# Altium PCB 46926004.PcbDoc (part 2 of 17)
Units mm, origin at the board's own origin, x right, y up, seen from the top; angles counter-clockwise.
Board outline 250 x 200 mm, 6 copper layers (Top Layer, INT1_GND, INT2_SIG, INT3_SIG, INT4_GND, Bottom Layer), stack 1.71 mm thick; 1450 components, 1293 nets, 5656 pads, 2307 vias.
Unrouted connection lines stored in the file: 2.
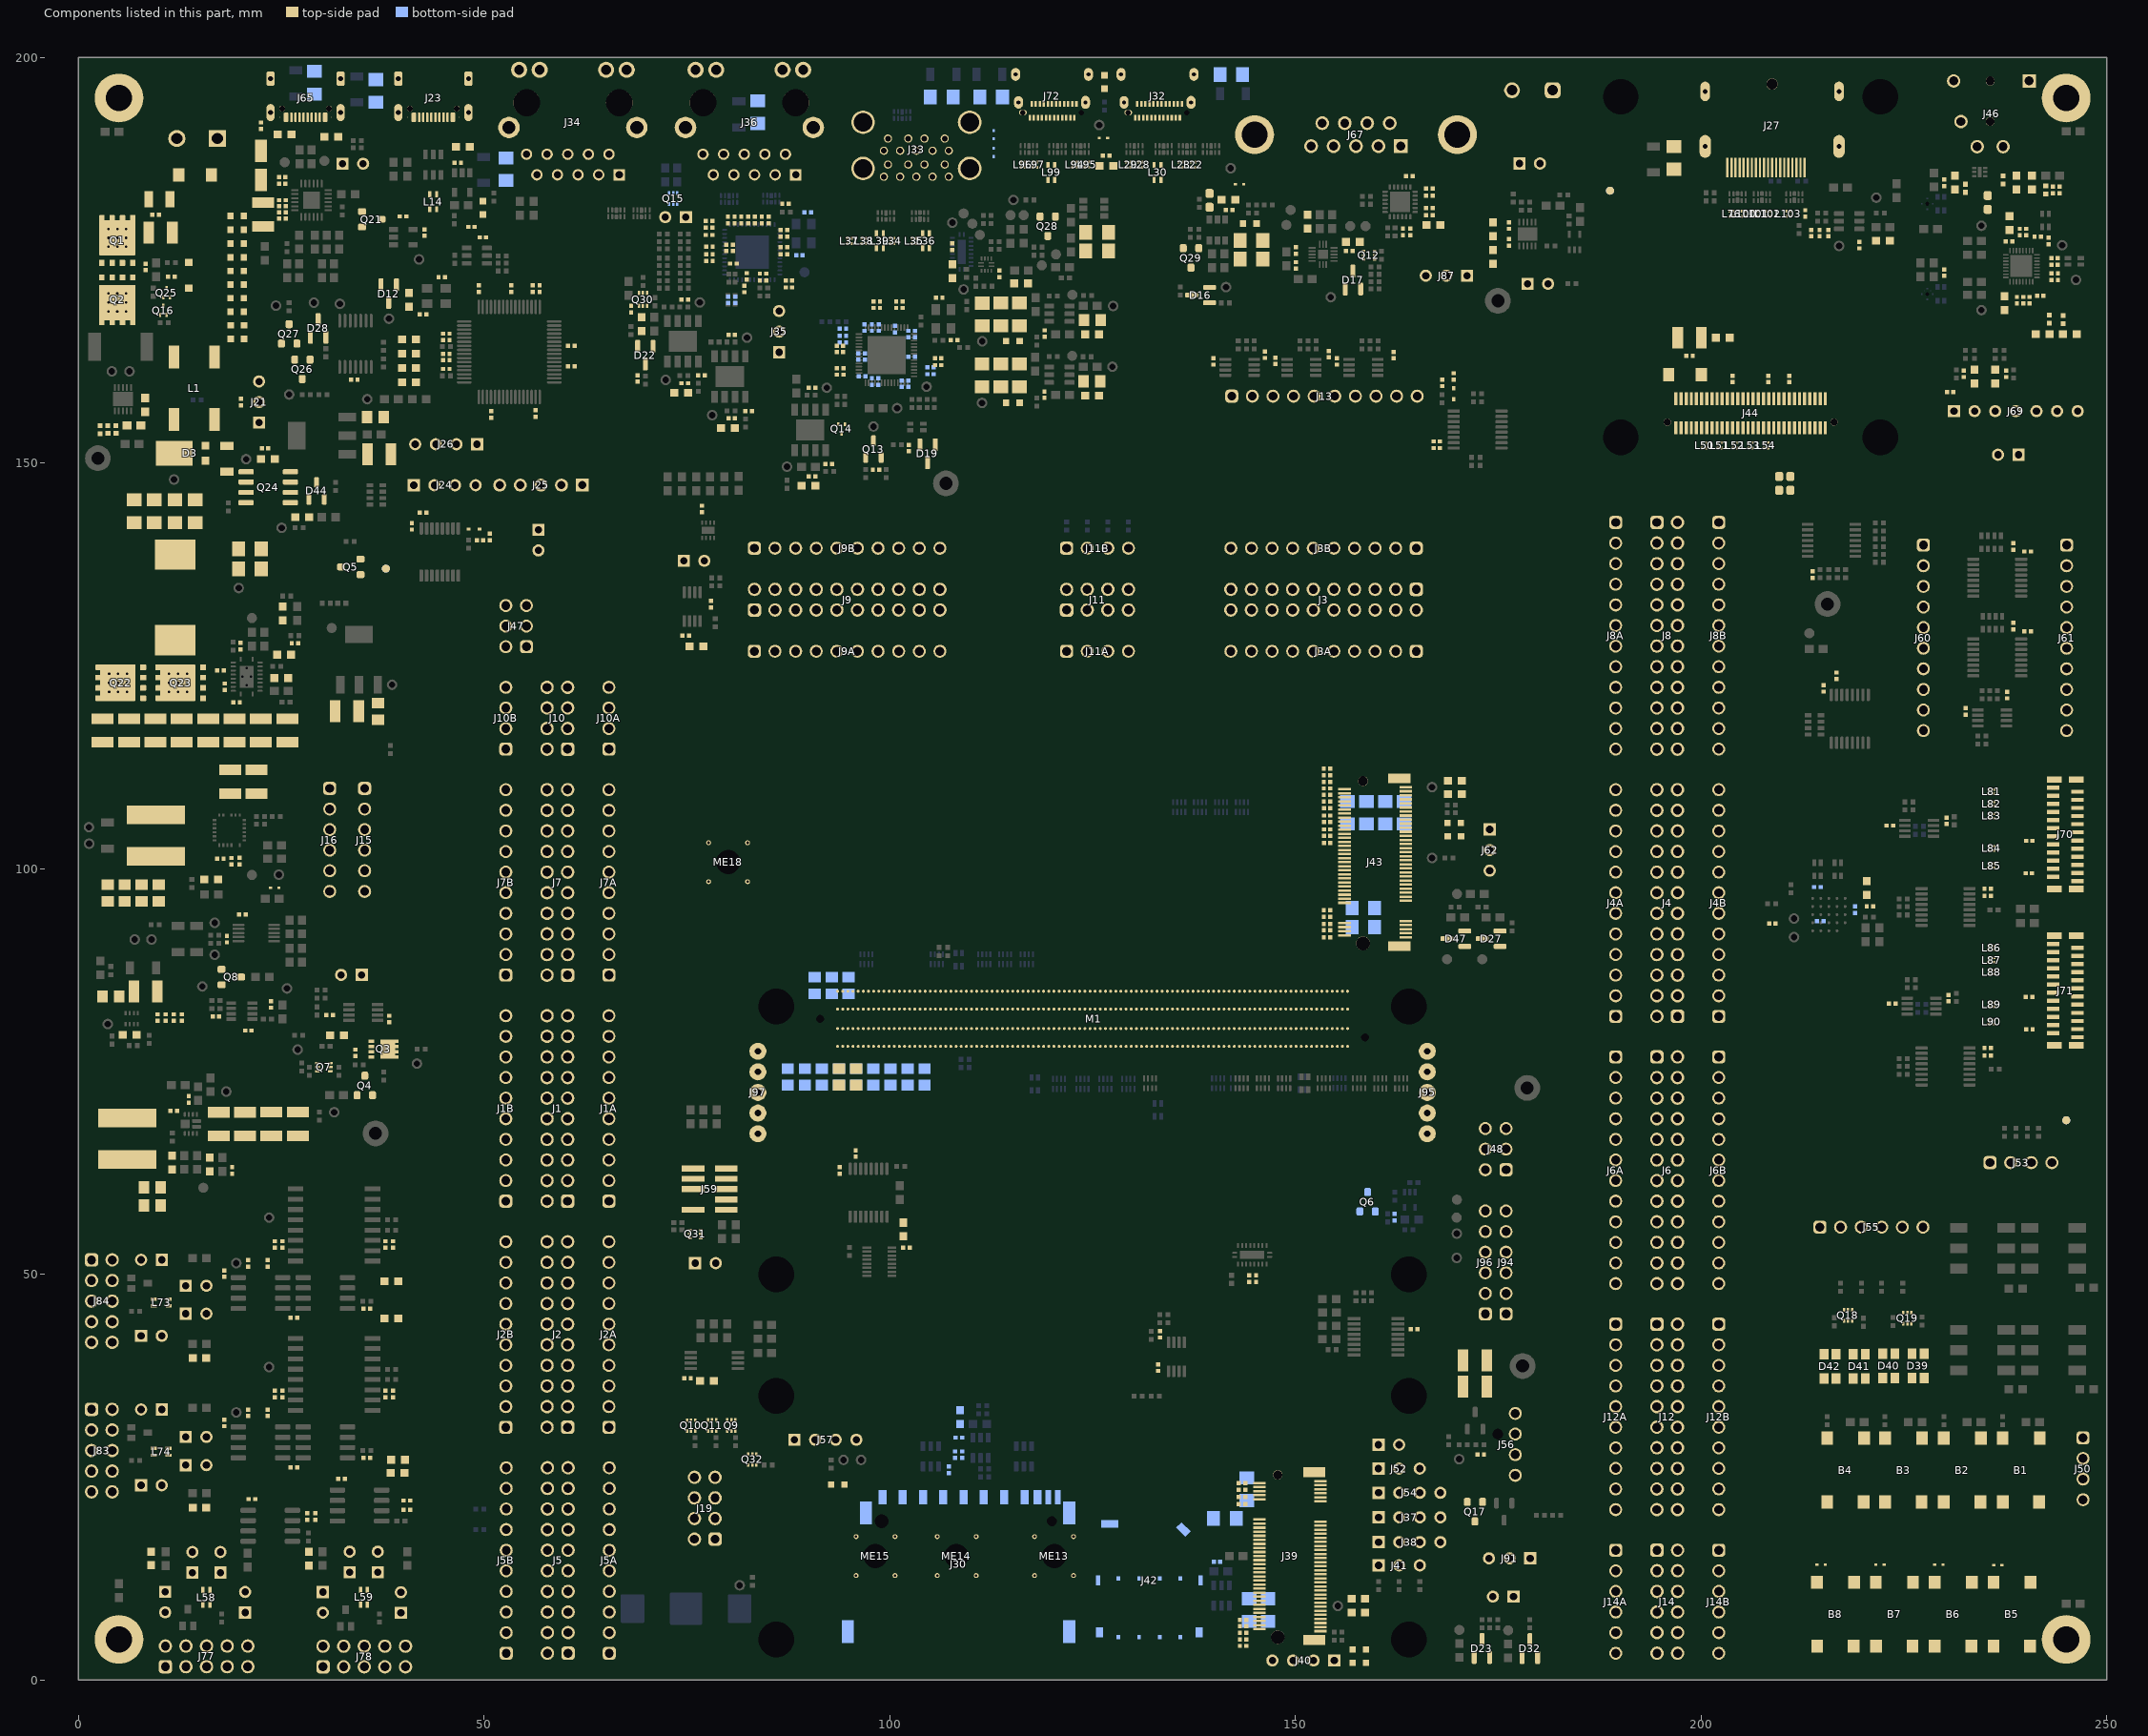
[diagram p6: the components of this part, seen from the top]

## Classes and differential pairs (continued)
differential pair PCIE_1_L1_RX: +PCIE_1_L1_RX_P -PCIE_1_L1_RX_N
differential pair FTUSB: +FTUSB_P -FTUSB_N
differential pair FT_USB: +FT_USB_P -FT_USB_N
differential pair ETH2_D3: +ETH2_D3_P -ETH2_D3_N
differential pair ETH2_D2: +ETH2_D2_P -ETH2_D2_N
differential pair ETH2_D1: +ETH2_D1_P -ETH2_D1_N
differential pair ETH2_D0: +ETH2_D0_P -ETH2_D0_N
differential pair DSI__D3: +DSI__D3_P -DSI__D3_N
differential pair DSI__D2: +DSI__D2_P -DSI__D2_N
differential pair DSI__D1: +DSI__D1_P -DSI__D1_N
differential pair DSI__D0: +DSI__D0_P -DSI__D0_N
differential pair DSI__CLK: +DSI__CLK_P -DSI__CLK_N
differential pair DP_1_LANE3: +DP_1_LANE3_P -DP_1_LANE3_N
differential pair DP_1_LANE2: +DP_1_LANE2_P -DP_1_LANE2_N
differential pair DP_1_LANE1: +DP_1_LANE1_P -DP_1_LANE1_N
differential pair DP_1_LANE0: +DP_1_LANE0_P -DP_1_LANE0_N
differential pair DP_1_AUX: +DP_1_AUX_P -DP_1_AUX_N
differential pair CSI_C2_D3: +CSI_C2_D3_P -CSI_C2_D3_N
differential pair CSI_C2_D2: +CSI_C2_D2_P -CSI_C2_D2_N
differential pair CSI_C2_D1: +CSI_C2_D1_P -CSI_C2_D1_N
differential pair CSI_C2_D0: +CSI_C2_D0_P -CSI_C2_D0_N
differential pair CSI_C2_CLK: +CSI_C2_CLK_P -CSI_C2_CLK_N
differential pair CSI_C1_D3: +CSI_C1_D3_P -CSI_C1_D3_N
differential pair CSI_C1_D2: +CSI_C1_D2_P -CSI_C1_D2_N
differential pair CSI_C1_D1: +CSI_C1_D1_P -CSI_C1_D1_N
differential pair CSI_C1_D0: +CSI_C1_D0_P -CSI_C1_D0_N
differential pair CSI_C1_CLK: +CSI_C1_CLK_P -CSI_C1_CLK_N
differential pair CSI_2_D3: +CSI_2_D3_P -CSI_2_D3_N
differential pair CSI_2_D2: +CSI_2_D2_P -CSI_2_D2_N
differential pair CSI_2_D1: +CSI_2_D1_P -CSI_2_D1_N
differential pair CSI_2_D0: +CSI_2_D0_P -CSI_2_D0_N
differential pair CSI_2_CLK: +CSI_2_CLK_P -CSI_2_CLK_N
differential pair USB_2_D: +USB_2_D_P -USB_2_D_N
differential pair USB_1_D: +USB_1_D_P -USB_1_D_N
differential pair PCIE_1_L0_TX: +PCIE_1_L0_TX_P -PCIE_1_L0_TX_N
differential pair PCIE_1_L0_RX: +PCIE_1_L0_RX_P -PCIE_1_L0_RX_N
differential pair PCIE_1_CLK: +PCIE_1_CLK_P -PCIE_1_CLK_N
differential pair ETH_1_MDI3: +ETH_1_MDI3_P -ETH_1_MDI3_N
differential pair ETH_1_MDI2: +ETH_1_MDI2_P -ETH_1_MDI2_N
differential pair ETH_1_MDI1: +ETH_1_MDI1_P -ETH_1_MDI1_N
differential pair ETH_1_MDI0: +ETH_1_MDI0_P -ETH_1_MDI0_N
differential pair DSI_1_D3: +DSI_1_D3_P -DSI_1_D3_N
differential pair DSI_1_D2: +DSI_1_D2_P -DSI_1_D2_N
differential pair DSI_1_D1: +DSI_1_D1_P -DSI_1_D1_N
differential pair DSI_1_D0: +DSI_1_D0_P -DSI_1_D0_N
differential pair DSI_1_CLK: +DSI_1_CLK_P -DSI_1_CLK_N
differential pair CSI_1_D3: +CSI_1_D3_P -CSI_1_D3_N
differential pair CSI_1_D2: +CSI_1_D2_P -CSI_1_D2_N
differential pair CSI_1_D1: +CSI_1_D1_P -CSI_1_D1_N
differential pair CSI_1_D0: +CSI_1_D0_P -CSI_1_D0_N
differential pair CSI_1_CLK: +CSI_1_CLK_P -CSI_1_CLK_N

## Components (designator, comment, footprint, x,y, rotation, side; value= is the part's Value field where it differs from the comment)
B1 "B3FS-1010P" OMRONSW_B3FS-1010P 239.448,25.875 r90 top
B2 "B3FS-1010P" OMRONSW_B3FS-1010P 232.198,25.875 r90 top
B3 "B3FS-1010P" OMRONSW_B3FS-1010P 224.948,25.875 r90 top
B4 "B3FS-1010P" OMRONSW_B3FS-1010P 217.823,25.875 r90 top
B5 "B3FS-1010P" OMRONSW_B3FS-1010P 238.325,8.1 r90 top locked
B6 "B3FS-1010P" OMRONSW_B3FS-1010P 231.075,8.1 r90 top locked
B7 "B3FS-1010P" OMRONSW_B3FS-1010P 223.825,8.1 r90 top locked
B8 "B3FS-1010P" OMRONSW_B3FS-1010P 216.575,8.1 r90 top locked
C1 "10uF/50V" CAPC3225N 33.1,119.425 r180 top
C2 "10uF/50V" CAPC3225N 10.125,178.425 r180 top
C3 "100nF" C0402_CAPC1005L 9.525,180.6 r0 top
C4 "1314-Cap-0805-22uF/16V" C/0805 36.925,119.375 r90 top value=22uF/16V
C5 "100nF" C0402_CAPC1005L 8.305,174.17 r270 top
C6 "1573-Cap-0402-1.5nF" C0402_CAPC1005L 11.46,172.97 r180 top value=1.5nF
C7 "100nF" C0402_CAPC1005L 20.025,157.525 r90 top
C8 "100nF" C0402_CAPC1005L 38.3,81.475 r90 top
C9 "100nF" C0402_CAPC1005L 30.977,81.975 r0 top
C10 "100nF" C0402_CAPC1005L 34.125,77.3 r90 top
C11 "100nF" C0402_CAPC1005L 18.3,91.325 r270 top
C12 "100nF" C0402_CAPC1005L 20.225,94.35 r180 top
C13 "1314-Cap-0805-22uF/16V" C/0805 9.128,60.725 r180 top value=22uF/16V
C14 "1314-Cap-0805-22uF/16V" C/0805 4,84.25 r0 top value=22uF/16V
C15 "1314-Cap-0805-22uF/16V" C/0805 9.128,58.475 r180 top value=22uF/16V
C16 "100nF" C/0603 6.324,79.535 r180 top value=470pF
C17 "100nF" C0402_CAPC1005L 13.6,71.575 r270 top
C18 "10uF/50V" CAPC3225N 172.125,39.4 r0 top
C19 "10uF/50V" CAPC3225N 172.125,36.15 r0 top
C20 "10uF/50V" CAPC3225N 18.7,110.725 r270 top
C21 "22uF/6.3V" C0402_CAPC1005L 12.755,81.653 r90 top
C22 "22uF/6.3V" C0402_CAPC1005L 18.866,100.925 r90 top
C23 "10uF/50V" CAPC3225N 21.925,110.725 r270 top
C24 "22uF/6.3V" C0402_CAPC1005L 11.755,81.653 r90 top
C25 "22uF/6.3V" C0402_CAPC1005L 10.755,81.653 r90 top
C26 "22uF/6.3V" C0402_CAPC1005L 9.755,81.653 r90 top
C27 "10nF" C0402_CAPC1005L 19.869,100.928 r90 top
C28 "100uF/10V" C/1206 144.57,177.436 r180 top
C29 "100nF" C0402_CAPC1005L 11.755,70.175 r0 top
C30 "2163-Cap-0603-10uF/16V" C/0603 11.525,63.8 r90 top value=10uF/16V
C31 "2093-Cap-0603-4.7uF/10V" C/0603 141.72,182.452 r180 top value=4.7uF/10V
C32 "100uF/10V" C/1206 115.984,160.805 r270 top
C33 "100uF/10V" C/1206 116,168.324 r270 top
C34 "100nF" C0402_CAPC1005L 17.491,101.25 r0 top
C35 "2093-Cap-0603-4.7uF/10V" C/0603 126.696,186.65 r180 top value=4.7uF/10V
C36 "0318-Cap-0402-1nF/50V" C0402_CAPC1005L 18.954,62.817 r90 top value=1nF
C37 "1567-Cap-0603-47pF/100V" C/0603 16.175,63.525 r270 top value=47pF
C38 "0213-Cap-0603-220pF/50V" C/0603 16.366,98.675 r180 top value=220pF
C39 "22uF/6.3V" C0402_CAPC1005L 40,180.4 r0 top
C40 "10uF/50V" CAPC3225N 27.032,68.531 r90 top
C41 "22uF/6.3V" C0402_CAPC1005L 42.666,178.411 r270 top
C42 "1647-Cap-0805-47uF/10V" C/0805 9.9,97 r90 top value=47uF/10V
C43 "10uF/50V" CAPC3225N 23.786,68.531 r90 top
C44 "1647-Cap-0805-47uF/10V" C/0805 7.8,97 r90 top value=47uF/10V
C45 "1647-Cap-0805-47uF/10V" C/0805 5.7,97 r90 top value=47uF/10V
C46 "1647-Cap-0805-47uF/10V" C/0805 3.6,97 r90 top value=47uF/10V
C47 "100nF" C0402_CAPC1005L 23.725,83.275 r270 top
C48 "100nF" C0402_CAPC1005L 20.95,80.05 r0 top
C49 "1644-Cap-0402-1uF/16V" C0402_CAPC1005L 16.95,81.775 r0 top value=1uF/16V
C50 "0000-Cap-0603-DNP" C/0603 31.875,79.45 r0 top value=DNP
C51 "14x 22uF/16V" C/0805 90.75,85.6 r270 bottom value=22uF/16V
C52 "1314-Cap-0805-22uF/16V" C/0805 91.639,74.35 r90 bottom value=22uF/16V
C53 "1314-Cap-0805-22uF/16V" C/0805 89.539,74.35 r90 bottom value=22uF/16V
C54 "1314-Cap-0805-22uF/16V" C/0805 87.425,74.35 r90 bottom value=22uF/16V
C55 "1314-Cap-0805-22uF/16V" C/0805 104.289,74.35 r90 bottom value=22uF/16V
C56 "1314-Cap-0805-22uF/16V" C/0805 93.739,74.35 r90 bottom value=22uF/16V
C57 "1314-Cap-0805-22uF/16V" C/0805 95.865,74.35 r90 top value=22uF/16V
C58 "1314-Cap-0805-22uF/16V" C/0805 93.739,74.35 r90 top value=22uF/16V
C59 "1314-Cap-0805-22uF/16V" C/0805 97.989,74.35 r90 bottom value=22uF/16V
C60 "1314-Cap-0805-22uF/16V" C/0805 100.089,74.35 r90 bottom value=22uF/16V
C61 "1314-Cap-0805-22uF/16V" C/0805 92.85,85.6 r270 bottom value=22uF/16V
C62 "1314-Cap-0805-22uF/16V" C/0805 95.865,74.35 r90 bottom value=22uF/16V
C63 "1314-Cap-0805-22uF/16V" C/0805 94.925,85.6 r270 bottom value=22uF/16V
C64 "1314-Cap-0805-22uF/16V" C/0805 102.189,74.35 r90 bottom value=22uF/16V
C65 "100nF" C0402_CAPC1005L 139.885,162.533 r270 top
C66 "100nF" C0402_CAPC1005L 147.515,162.6 r270 top
C67 "100nF" C0402_CAPC1005L 146.234,163.355 r270 top
C68 "100nF" C0402_CAPC1005L 154.097,163.42 r270 top
C69 "100nF" C0402_CAPC1005L 155.125,162.533 r270 top
C70 "100nF" C0402_CAPC1005L 162.1,163.3 r270 top
C71 "0567-Cap-1206-1nF/2KV" C/1206 36.65,195.86 r270 bottom value=1nF/2KV
C72 "22uF/6.3V" C0402_CAPC1005L 46.753,187.03 r0 top
C73 "22uF/6.3V" C0402_CAPC1005L 48.437,179.109 r0 top
C74 "100nF" C0402_CAPC1005L 49.85,177.816 r0 top
C75 "22uF/6.3V" C0402_CAPC1005L 45.34,162.7 r0 top
C76 "22uF/6.3V" C0402_CAPC1005L 45.34,165.175 r0 top
C77 "1555-Cap-0402-20pF" C0402_CAPC1005L 42.49,168.325 r180 top value=20pF
C78 "100nF" C0402_CAPC1005L 56,171.5 r270 top
C79 "100nF" C0402_CAPC1005L 45.34,163.475 r0 top
C80 "100nF" C0402_CAPC1005L 45.34,165.95 r0 top
C81 "1555-Cap-0402-20pF" C0402_CAPC1005L 44.79,172.9 r180 top value=20pF
C82 "22uF/6.3V" C0402_CAPC1005L 56.85,171.5 r270 top
C83 "100nF" C0402_CAPC1005L 45.34,161.6 r0 top
C84 "100nF" C0402_CAPC1005L 60.75,161.95 r180 top
C85 "100nF" C0402_CAPC1005L 50.865,156 r90 top
C86 "100nF" C0402_CAPC1005L 49.34,171.5 r270 top
C87 "100nF" C0402_CAPC1005L 56.365,156.1 r90 top
C88 "100nF" C0402_CAPC1005L 60.75,164.45 r180 top
C89 "100nF" C0402_CAPC1005L 53.34,171.5 r270 top
C90 "22uF/6.3V" C0402_CAPC1005L 108.514,29.88 r0 bottom
C91 "100nF" C0402_CAPC1005L 107.3,25.92 r90 bottom
C92 "100nF" C0402_CAPC1005L 74.85,128.755 r0 top
C93 "100nF" C0402_CAPC1005L 77.96,132.613 r90 top
C94 "0354-Cap-0402-4.7uF/6.3V" C0402_CAPC1005L 150.071,176.215 r270 top value=4.7uF/6.3V
C95 "2234-Cap-0402-2.2uF/10V" C0402_CAPC1005L 150.071,174.365 r90 top value=2.2uF/10V
C96 "0354-Cap-0402-4.7uF/6.3V" C0402_CAPC1005L 68.124,168.989 r90 top value=4.7uF/6.3V
C97 "100nF" C0402_CAPC1005L 156.646,176.123 r180 top
C98 "0000-Cap-0603-DNP" C/0603 69.441,167.11 r90 top value=DNP
C99 "100nF" C0402_CAPC1005L 86.95,177.925 r0 top
C100 "100nF" C0402_CAPC1005L 141.828,181.2 r180 top
C101 "0567-Cap-1206-1nF/2KV" C/1206 142.1,197.9 r180 bottom value=1nF/2KV
C102 "0354-Cap-0402-4.7uF/6.3V" C0402_CAPC1005L 98.659,166.7 r90 bottom value=4.7uF/6.3V
C103 "0354-Cap-0402-4.7uF/6.3V" C0402_CAPC1005L 102.7,163.118 r0 bottom value=4.7uF/6.3V
C104 "0354-Cap-0402-4.7uF/6.3V" C0402_CAPC1005L 102.375,151.849 r90 top value=4.7uF/6.3V
C105 "0354-Cap-0402-4.7uF/6.3V" C0402_CAPC1005L 94.222,166.56 r0 bottom value=4.7uF/6.3V
C106 "0354-Cap-0402-4.7uF/6.3V" C0402_CAPC1005L 105.024,161.8 r180 bottom value=4.7uF/6.3V
C107 "100nF" C0402_CAPC1005L 100.637,166.5 r90 bottom
C108 "22uF/6.3V" C0402_CAPC1005L 90.426,148.359 r0 top
C109 "100nF" C0402_CAPC1005L 97.794,166.7 r90 bottom
C110 "22uF/6.3V" C0402_CAPC1005L 92.486,149.866 r180 top
C111 "100nF" C0402_CAPC1005L 97.796,160.04 r270 bottom
C112 "100nF" C0402_CAPC1005L 98.576,160.04 r270 bottom
C113 "100nF" C0402_CAPC1005L 94.222,164.86 r0 bottom
C114 "100nF" C0402_CAPC1005L 96.905,166.7 r90 bottom
C115 "100nF" C0402_CAPC1005L 102.7,165.5 r0 bottom
C116 "100nF" C0402_CAPC1005L 96.534,162.735 r180 bottom
C117 "100nF" C0402_CAPC1005L 105.967,162.075 r180 top
C118 "100nF" C0402_CAPC1005L 94.222,165.694 r0 bottom
C119 "100nF" C0402_CAPC1005L 96.534,163.493 r180 bottom
C120 "100nF" C0402_CAPC1005L 105.967,162.939 r180 top
C121 "0318-Cap-0402-1nF/50V" C0402_CAPC1005L 102.7,166.3 r180 bottom value=1nF
C122 "22uF/6.3V" C0402_CAPC1005L 90.426,159.282 r0 top
C123 "100nF" C0402_CAPC1005L 96.593,160.693 r180 bottom
C124 "0318-Cap-0402-1nF/50V" C0402_CAPC1005L 105.024,160.953 r0 bottom value=1nF
C125 "0318-Cap-0402-1nF/50V" C0402_CAPC1005L 101.875,159.375 r180 bottom value=1nF
C126 "1554-Cap-0402-30pF" C0402_CAPC1005L 106.095,170.37 r0 top value=30pF
C127 "0318-Cap-0402-1nF/50V" C0402_CAPC1005L 101.875,160.175 r180 bottom value=1nF
C128 "1554-Cap-0402-30pF" C0402_CAPC1005L 107.942,165.138 r0 top value=30pF
C129 "100nF" C0402_CAPC1005L 98.311,149.198 r0 top
C130 "100nF" C0402_CAPC1005L 77.725,178.11 r180 top
C131 "100nF" C0402_CAPC1005L 100.792,169.525 r270 top
C132 "100nF" C0402_CAPC1005L 97.992,169.525 r270 top
C133 "100nF" C0402_CAPC1005L 93.867,163.7 r0 top
C134 "100nF" C0402_CAPC1005L 93.892,160.897 r0 top
C135 "100nF" C0402_CAPC1005L 101.567,169.525 r270 top
C136 "100nF" C0402_CAPC1005L 98.792,169.525 r270 top
C137 "100nF" C0402_CAPC1005L 93.867,164.45 r0 top
C138 "100nF" C0402_CAPC1005L 93.892,161.697 r0 top
C139 "22uF/6.3V" C/0805 124.931,160.082 r180 top value=22uF/16V
C140 "22uF/6.3V" C/0805 124.95,167.613 r180 top value=22uF/16V
C141 "1644-Cap-0402-1uF/16V" C0402_CAPC1005L 86.95,178.725 r180 top value=1uF/16V
C142 "1644-Cap-0402-1uF/16V" C0402_CAPC1005L 77.725,179.01 r0 top value=1uF/16V
C143 "1646-Cap-0402-10uF/6.3V" C0402_CAPC1005L 77.725,179.86 r0 top value=10uF/6.3V
C144 "100nF" C0402_CAPC1005L 229.95,184.55 r270 top
C145 "100nF" C0402_CAPC1005L 119.069,158.43 r90 top
C146 "100nF" C0402_CAPC1005L 119.112,165.959 r90 top
C147 "100nF" C0402_CAPC1005L 80.95,170.125 r270 bottom
C148 "0567-Cap-1206-1nF/2KV" C/1206 52.7,186.22 r90 bottom value=1nF/2KV
C149 "22uF/6.3V" C0402_CAPC1005L 74.725,159.844 r0 top
C150 "22uF/6.3V" C0402_CAPC1005L 80.53,155.507 r0 top
C151 "22uF/6.3V" C0402_CAPC1005L 76.795,160.792 r180 top
C152 "22uF/6.3V" C0402_CAPC1005L 82.6,156.4 r180 top
C153 "22uF/6.3V" C0402_CAPC1005L 74.725,170.146 r0 top
C154 "22uF/6.3V" C0402_CAPC1005L 80.53,165.817 r0 top
C155 "100nF" C0402_CAPC1005L 68.932,160.424 r270 top
C156 "1646-Cap-0402-10uF/6.3V" C0402_CAPC1005L 77.775,174.9 r0 top value=10uF/6.3V
C157 "1646-Cap-0402-10uF/6.3V" C0402_CAPC1005L 79.85,176.525 r270 top value=10uF/6.3V
C158 "1644-Cap-0402-1uF/16V" C0402_CAPC1005L 83.375,179.975 r270 top value=1uF/16V
C159 "1554-Cap-0402-30pF" C0402_CAPC1005L 88.872,175.63 r0 bottom value=30pF
C160 "1644-Cap-0402-1uF/16V" C0402_CAPC1005L 87.575,171.647 r180 top value=1uF/16V
C161 "1644-Cap-0402-1uF/16V" C0402_CAPC1005L 80.65,176.525 r270 top value=1uF/16V
C162 "1554-Cap-0402-30pF" C0402_CAPC1005L 89.9,180.9 r180 bottom value=30pF
C163 "1646-Cap-0402-10uF/6.3V" C0402_CAPC1005L 80.875,179.975 r270 top value=10uF/6.3V
C164 "1644-Cap-0402-1uF/16V" C0402_CAPC1005L 82.371,173.012 r270 top value=1uF/16V
C165 "1644-Cap-0402-1uF/16V" C0402_CAPC1005L 84.388,173.35 r180 top value=1uF/16V
C166 "1644-Cap-0402-1uF/16V" C0402_CAPC1005L 80.05,179.975 r270 top value=1uF/16V
C167 "1644-Cap-0402-1uF/16V" C0402_CAPC1005L 77.775,176.65 r0 top value=1uF/16V
C168 "1644-Cap-0402-1uF/16V" C0402_CAPC1005L 86.95,176.6 r180 top value=1uF/16V
C169 "1644-Cap-0402-1uF/16V" C0402_CAPC1005L 85.075,179.975 r270 top value=1uF/16V
C170 "100nF" C0402_CAPC1005L 82.55,179.975 r90 top
C171 "100nF" C0402_CAPC1005L 80.725,174.585 r0 top
C172 "100nF" C0402_CAPC1005L 81.7,179.975 r90 top
C173 "100nF" C0402_CAPC1005L 87.575,172.497 r0 top
C174 "100nF" C0402_CAPC1005L 84.388,172.525 r0 top
C175 "100nF" C0402_CAPC1005L 84.225,179.975 r90 top
C176 "100nF" C0402_CAPC1005L 82.065,171.458 r270 top
C177 "1554-Cap-0402-30pF" C0402_CAPC1005L 87.151,181.948 r0 top value=30pF
C178 "100nF" C0402_CAPC1005L 86.95,175.75 r0 top
C179 "100nF" C0402_CAPC1005L 77.775,175.75 r180 top
C180 "1941-Cap-1206-47uF/10V" C/1206 14.39,144.055 r270 top value=47uF/10V
C181 "1941-Cap-1206-47uF/10V" C/1206 11.89,144.055 r270 top value=47uF/10V
C182 "100nF" C0402_CAPC1005L 229.95,173.475 r270 top
C183 "1941-Cap-1206-47uF/10V" C/1206 21.14,136.94 r180 top value=47uF/10V
C184 "0665-Cap-0603-470pF/50V" C/0603 238.875,184.55 r90 top value=470pF
C185 "1941-Cap-1206-47uF/10V" C/1206 21.14,139.44 r180 top value=47uF/10V
C186 "0567-Cap-1206-1nF/2KV" C/1206 83.725,193.265 r90 bottom value=1nF/2KV
C187 "1941-Cap-1206-47uF/10V" C/1206 9.362,144.055 r270 top value=47uF/10V
C188 "100nF" C0402_CAPC1005L 80.1,170.125 r270 bottom
C189 "0665-Cap-0603-470pF/50V" C/0603 231.3,184.55 r90 top value=470pF
C190 "100uF/10V" C/1206 111.36,160.805 r270 top
C191 "100uF/10V" C/1206 111.387,168.314 r270 top
C192 "100nF" C0402_CAPC1005L 143.555,7.425 r0 top
C193 "100nF" C0402_CAPC1005L 143.415,23.425 r0 top
C194 "100nF" C0402_CAPC1005L 143.555,6.625 r0 top
C195 "100nF" C0402_CAPC1005L 143.418,24.275 r0 top
C196 "100nF" C0402_CAPC1005L 145.156,49.485 r270 top
C197 "100nF" C0402_CAPC1005L 140.341,14.592 r0 bottom
C198 "100uF/10V" C/1206 113.684,160.805 r270 top
C199 "100uF/10V" C/1206 113.675,168.324 r270 top
C200 "100nF" C0402_CAPC1005L 153.893,110.693 r0 top
C201 "100nF" C0402_CAPC1005L 153.893,109.9 r0 top
C202 "100nF" C0402_CAPC1005L 153.893,109.084 r0 top
C203 "100nF" C0402_CAPC1005L 153.893,108.3 r0 top
C204 "100nF" C0402_CAPC1005L 208.3,160.375 r270 top
C205 "10uF/50V" CAPC3225N 198.572,165.45 r0 top
C206 "100nF" C0402_CAPC1005L 203.872,160.375 r270 top
C207 "100nF" C0402_CAPC1005L 210.85,160.375 r270 top
C208 "100nF" C0402_CAPC1005L 198.572,163.2 r0 top
C209 "100nF" C0402_CAPC1005L 32.425,24.8 r180 top
C210 "100nF" C0402_CAPC1005L 21.4,22.3 r180 top
C211 "100nF" C0402_CAPC1005L 40.475,21 r180 top
C212 "100nF" C0402_CAPC1005L 28.225,20.15 r270 top
C213 "1644-Cap-0402-1uF/16V" C0402_CAPC1005L 40.475,22.125 r180 top value=1uF/16V
C214 "1644-Cap-0402-1uF/16V" C0402_CAPC1005L 29.2,20.15 r270 top value=1uF/16V
C215 "1470-Cap-0603-3.6nF" C/0603 8.961,14.984 r90 top value=3.6nF
C216 "1470-Cap-0603-3.6nF" C/0603 28.4,14.971 r90 top value=3.6nF
C217 "100nF" C0402_CAPC1005L 240.075,178.475 r270 top
C218 "100nF" C0402_CAPC1005L 238.925,170.075 r90 top
C219 "100nF" C0402_CAPC1005L 239.7,170.075 r90 top
C220 "0354-Cap-0402-4.7uF/6.3V" C0402_CAPC1005L 237.965,177.335 r0 top value=4.7uF/6.3V
C221 "0354-Cap-0402-4.7uF/6.3V" C0402_CAPC1005L 240.475,170.075 r90 top value=4.7uF/6.3V
C222 "0354-Cap-0402-4.7uF/6.3V" C0402_CAPC1005L 239.275,178.475 r270 top value=4.7uF/6.3V
C223 "100nF" C0402_CAPC1005L 243.56,175.275 r180 top
C224 "100nF" C0402_CAPC1005L 243.56,174.45 r180 top
C225 "2234-Cap-0402-2.2uF/10V" C0402_CAPC1005L 241.8,170.6 r180 top value=2.2uF/10V
C226 "2234-Cap-0402-2.2uF/10V" C0402_CAPC1005L 243.575,173.4 r180 top value=2.2uF/10V
C227 "2234-Cap-0402-2.2uF/10V" C0402_CAPC1005L 243.575,172.575 r180 top value=2.2uF/10V
C228 "100nF" C0402_CAPC1005L 76.87,144.338 r270 top
C229 "100nF" C0402_CAPC1005L 208.785,93.226 r0 top
C230 "0354-Cap-0402-4.7uF/6.3V" C0402_CAPC1005L 220.812,95.35 r180 top value=4.7uF/6.3V
C231 "100nF" C0402_CAPC1005L 214.675,93.53 r180 bottom
C232 "100nF" C0402_CAPC1005L 214.348,97.74 r0 bottom
C233 "100nF" C0402_CAPC1005L 75.075,37.215 r0 top
C234 "100nF" C0402_CAPC1005L 133.063,38.5 r90 top
C235 "100nF" C0402_CAPC1005L 133.323,42.613 r90 top
C236 "100nF" C0402_CAPC1005L 164.637,43.248 r180 top
C237 "100nF" C0402_CAPC1005L 172.837,27.775 r0 top
C238 "100nF" C0402_CAPC1005L 102.05,53.3 r180 top
C239 "100nF" C0402_CAPC1005L 93.814,62.814 r90 top
C240 "100nF" C0402_CAPC1005L 95.8,64.9 r270 top
C241 "100nF" C0402_CAPC1005L 240.25,129.275 r180 top
C242 "100nF" C0402_CAPC1005L 215.1,122.225 r270 top
C243 "100nF" C0402_CAPC1005L 238.5,129.9 r270 top
C244 "100nF" C0402_CAPC1005L 216.707,123.779 r270 top
C245 "100nF" C0402_CAPC1005L 240.25,139.1 r180 top
C246 "100nF" C0402_CAPC1005L 238.5,139.725 r270 top
C247 "22uF/6.3V" C0402_CAPC1005L 38.8,53.68 r90 top
C248 "22uF/6.3V" C0402_CAPC1005L 38.8,35.265 r90 top
C249 "100nF" C0402_CAPC1005L 37.85,53.68 r90 top
C250 "100nF" C0402_CAPC1005L 37.85,35.265 r90 top
C251 "100nF" C0402_CAPC1005L 35.55,45.775 r180 top
C252 "100nF" C0402_CAPC1005L 35.55,27.375 r180 top
C253 "22uF/6.3V" C0402_CAPC1005L 20.9,32.935 r270 top
C254 "100nF" C0402_CAPC1005L 25.14,53.68 r90 top
C255 "22uF/6.3V" C0402_CAPC1005L 20.9,51.35 r270 top
C256 "100nF" C0402_CAPC1005L 25.14,35.265 r90 top
C257 "22uF/6.3V" C0402_CAPC1005L 24.2,53.685 r90 top
C258 "22uF/6.3V" C0402_CAPC1005L 24.2,35.265 r90 top
C259 "100nF" C0402_CAPC1005L 23.325,32.935 r270 top
C260 "100nF" C0402_CAPC1005L 18,31.69 r270 top
C261 "100nF" C0402_CAPC1005L 17.985,50.085 r270 top
C262 "100nF" C0402_CAPC1005L 23.33,51.35 r270 top
C263 "1470-Cap-0603-3.6nF" C/0603 14.925,39.667 r0 top value=3.6nF
C264 "1470-Cap-0603-3.6nF" C/0603 14.925,21.25 r0 top value=3.6nF
C265 "10uF/50V" CAPC3225N 25.742,117.025 r90 top
C266 "10uF/50V" CAPC3225N 22.492,117.025 r90 top
C267 "1554-Cap-0402-30pF" C0402_CAPC1005L 19.992,127.425 r90 top value=30pF
C268 "1573-Cap-0402-1.5nF" C0402_CAPC1005L 26.692,127.773 r0 top value=1.5nF
C269 "0913-Cap-0603-47nF/50V-X7R" C/0603 25.013,123.502 r0 top value=47nF
C270 "100nF" C0402_CAPC1005L 19.492,120.5 r180 top
C271 "2234-Cap-0402-2.2uF/10V" C0402_CAPC1005L 17.51,124.43 r0 top value=2.2uF/10V
C272 "10uF/50V" CAPC3225N 19.242,117.025 r90 top
C273 "10uF/50V" CAPC3225N 15.992,117.025 r90 top
C274 "10uF/50V" CAPC3225N 12.742,117.025 r90 top
C275 "10uF/50V" CAPC3225N 9.492,117.025 r90 top
C276 "100nF" C0402_CAPC1005L 18.04,122.425 r90 top
C277 "1567-Cap-0603-47pF/100V" C/0603 25.342,126.382 r180 top value=47pF
C278 "10uF/50V" CAPC3225N 2.992,117.025 r90 top
C279 "1717-Cap-0603-560pF/25V" C/0603 25.196,131.475 r270 top value=560pF
C280 "0354-Cap-0402-4.7uF/6.3V" C0402_CAPC1005L 108.066,27.77 r270 bottom value=4.7uF/6.3V
C281 "10uF/50V" CAPC3225N 6.242,117.025 r90 top
C282 "0354-Cap-0402-4.7uF/6.3V" C0402_CAPC1005L 108.924,27.77 r270 bottom value=4.7uF/6.3V
C283 "1941-Cap-1206-47uF/10V" C/1206 6.862,144.055 r270 top value=47uF/10V
C284 "10uF/50V" CAPC3225N 37.075,151.075 r180 top
C285 "1314-Cap-0805-22uF/16V" C/0805 36.625,155.675 r180 top value=22uF/16V
C286 "100nF" C0402_CAPC1005L 144.321,49.485 r270 top
C287 "100nF" C0402_CAPC1005L 34,160.3 r180 top
C288 "0567-Cap-1206-1nF/2KV" C/1206 29.1,196.875 r90 bottom value=1nF/2KV
C289 "10nF" C0402_CAPC1005L 22.5,191.575 r270 top
C290 "0105-Cap-0603-330pF/100V" C/0603 31.175,190.225 r0 top value=330pF
C291 "0105-Cap-0603-330pF/100V" C/0603 25.4,190.5 r180 top value=330pF
C292 "100nF" C0402_CAPC1005L 25.15,182.4 r0 top
C293 "10uF/50V" CAPC3225N 22.76,180.64 r90 top
C294 "100nF" C0402_CAPC1005L 25.15,181.65 r0 top
C295 "1644-Cap-0402-1uF/16V" C0402_CAPC1005L 25.15,180.9 r0 top value=1uF/16V
C296 "100nF" C0402_CAPC1005L 25.525,184.85 r270 top
C297 "100nF" C0402_CAPC1005L 24.725,184.85 r270 top
C298 "1644-Cap-0402-1uF/16V" C0402_CAPC1005L 25.15,180.15 r0 top value=1uF/16V
C299 "1548-Cap-0603-1uF/50V" C/0603 27.56,143.33 r0 top value=1uF
C300 "1548-Cap-0603-1uF/50V" C/0603 23.35,150.475 r0 top value=1uF
C301 "100nF" C0402_CAPC1005L 23,151.825 r180 top
C302 "100nF" C0402_CAPC1005L 176.3,177.19 r270 top
C303 "100nF" C0402_CAPC1005L 164.051,185.384 r0 top
C304 "100nF" C0402_CAPC1005L 164.15,178.5 r270 top
C305 "100nF" C0402_CAPC1005L 166.5,182.95 r0 top
C306 "100nF" C0402_CAPC1005L 166.5,180.55 r0 top
C307 "100nF" C0402_CAPC1005L 163.249,178.5 r270 top
C308 "100nF" C0402_CAPC1005L 176.3,179.279 r270 top
C309 "100nF" C0402_CAPC1005L 166.5,183.835 r0 top
C310 "100nF" C0402_CAPC1005L 166.5,181.45 r0 top
C311 "100nF" C0402_CAPC1005L 223.266,105.315 r0 top
C312 "100nF" C0402_CAPC1005L 235.33,97.55 r180 top
C313 "100nF" C0402_CAPC1005L 235.33,96.659 r180 top
C314 "100nF" C0402_CAPC1005L 230.233,105.903 r270 top
C315 "100nF" C0402_CAPC1005L 240.45,103.435 r0 top
C316 "100nF" C0402_CAPC1005L 240.394,99.441 r0 top
C317 "100nF" C0402_CAPC1005L 223.551,83.39 r0 top
C318 "100nF" C0402_CAPC1005L 235.329,77.898 r180 top
C319 "100nF" C0402_CAPC1005L 235.326,76.977 r180 top
C320 "100nF" C0402_CAPC1005L 230.47,84.05 r270 top
C321 "100nF" C0402_CAPC1005L 240.429,84.196 r0 top
C322 "100nF" C0402_CAPC1005L 240.463,80.175 r0 top
C323 "100nF" C0402_CAPC1005L 107.71,176.675 r270 top
C324 "100nF" C0402_CAPC1005L 113.495,173.311 r90 top
C325 "100uF/10V" C/1206 125.546,178.45 r180 top
C326 "100nF" C0402_CAPC1005L 241.5,177.925 r180 top
C327 "0354-Cap-0402-4.7uF/6.3V" C0402_CAPC1005L 244.175,183.675 r270 top value=4.7uF/6.3V
C328 "100nF" C0402_CAPC1005L 126.685,187.9 r180 top
C329 "0567-Cap-1206-1nF/2KV" C/1206 112.49,195.135 r0 bottom value=1nF/2KV
C330 "0567-Cap-1206-1nF/2KV" C/1206 106.41,195.135 r180 bottom value=1nF/2KV
C331 "10uF/50V" CAPC3225N 17.28,68.525 r90 top
C332 "10uF/50V" CAPC3225N 20.53,68.525 r90 top
C333 "100nF" C0402_CAPC1005L 242.85,177.375 r270 top
C334 "1644-Cap-0402-1uF/16V" C0402_CAPC1005L 243.35,183.675 r270 top value=1uF/16V
C335 "1646-Cap-0402-10uF/6.3V" C0402_CAPC1005L 237.6,161 r270 top value=10uF/6.3V
C336 "0665-Cap-0603-470pF/50V" C/0603 240.775,184.55 r90 top value=470pF
C337 "1646-Cap-0402-10uF/6.3V" C0402_CAPC1005L 232.35,161 r270 top value=10uF/6.3V
C338 "0665-Cap-0603-470pF/50V" C/0603 245.45,165.9 r180 top value=470pF
C339 "0213-Cap-0603-220pF/50V" C/0603 236.25,160.65 r90 top value=220pF
C340 "0213-Cap-0603-220pF/50V" C/0603 233.7,160.65 r90 top value=220pF
C341 "0665-Cap-0603-470pF/50V" C/0603 242.075,165.9 r0 top value=470pF
C342 "100nF" C0402_CAPC1005L 230.7,158.775 r0 top
C343 "100uF/10V" C/1206 144.57,175.136 r180 top
C344 "100uF/10V" C/1206 125.546,176.146 r180 top
C345 "100nF" C0402_CAPC1005L 212.835,180.767 r90 top
C346 "0567-Cap-1206-1nF/2KV" C/1206 196.65,187.617 r90 top value=1nF/2KV
C347 "22uF/6.3V" C0402_CAPC1005L 219.525,176.867 r90 top
C348 "0354-Cap-0402-4.7uF/6.3V" C0402_CAPC1005L 215.675,178.342 r90 top value=4.7uF/6.3V
C349 "0354-Cap-0402-4.7uF/6.3V" C0402_CAPC1005L 214.6,178.342 r90 top value=4.7uF/6.3V
C350 "100nF" C0402_CAPC1005L 213.55,178.342 r90 top
C351 "100nF" C0402_CAPC1005L 232.625,119.4 r270 top
C352 "100nF" C0402_CAPC1005L 237.7,121.4 r270 top
C353 "100nF" C0402_CAPC1005L 167.423,152.675 r0 top
C354 "100nF" C0402_CAPC1005L 167.423,151.85 r0 top
C355 "2093-Cap-0603-4.7uF/10V" C/0603 151.496,179.74 r270 top value=4.7uF/10V
C356 "100nF" C0402_CAPC1005L 26.555,44.64 r0 top
C357 "100nF" C0402_CAPC1005L 26.548,26.223 r0 top
C358 "100nF" C0402_CAPC1005L 162.232,57.059 r90 bottom
C359 "100nF" C0402_CAPC1005L 213.725,136.26 r270 top
C360 "100nF" C0402_CAPC1005L 218.995,94.955 r90 bottom
C361 "0455-Cap-1206-100uF/6.3V" C/1206 146.63,8.622 r270 bottom value=100uF/6.3V
C362 "0455-Cap-1206-100uF/6.3V" C/1206 144.014,23.525 r270 bottom value=100uF/6.3V
C363 "0455-Cap-1206-100uF/6.3V" C/1206 144.314,8.622 r270 bottom value=100uF/6.3V
C364 "0455-Cap-1206-100uF/6.3V" C/1206 141.308,19.905 r0 bottom value=100uF/6.3V
C365 "1646-Cap-0402-10uF/6.3V" C0402_CAPC1005L 143.558,5.805 r0 top value=10uF/6.3V
C366 "1646-Cap-0402-10uF/6.3V" C0402_CAPC1005L 143.418,22.575 r0 top value=10uF/6.3V
C367 "1646-Cap-0402-10uF/6.3V" C0402_CAPC1005L 143.555,5.015 r0 top value=10uF/6.3V
C368 "1646-Cap-0402-10uF/6.3V" C0402_CAPC1005L 143.418,21.7 r0 top value=10uF/6.3V
C369 "1646-Cap-0402-10uF/6.3V" C0402_CAPC1005L 143.555,4.2 r0 top value=10uF/6.3V
C370 "0455-Cap-1206-100uF/6.3V" C/1206 163.4,106.9 r90 bottom value=100uF/6.3V
C371 "0455-Cap-1206-100uF/6.3V" C/1206 158.375,92.8 r180 bottom value=100uF/6.3V
C372 "0455-Cap-1206-100uF/6.3V" C/1206 161.076,106.9 r90 bottom value=100uF/6.3V
C373 "0455-Cap-1206-100uF/6.3V" C/1206 158.375,95.156 r180 bottom value=100uF/6.3V
C374 "1646-Cap-0402-10uF/6.3V" C0402_CAPC1005L 153.9,104.05 r0 top value=10uF/6.3V
C375 "1646-Cap-0402-10uF/6.3V" C0402_CAPC1005L 153.893,94.896 r0 top value=10uF/6.3V
C376 "1646-Cap-0402-10uF/6.3V" C0402_CAPC1005L 153.9,103.15 r0 top value=10uF/6.3V
C377 "1646-Cap-0402-10uF/6.3V" C0402_CAPC1005L 153.893,94.049 r0 top value=10uF/6.3V
C378 "1646-Cap-0402-10uF/6.3V" C0402_CAPC1005L 153.893,112.329 r0 top value=10uF/6.3V
C379 "1646-Cap-0402-10uF/6.3V" C0402_CAPC1005L 153.897,93.2 r0 top value=10uF/6.3V
C380 "1646-Cap-0402-10uF/6.3V" C0402_CAPC1005L 153.893,111.529 r0 top value=10uF/6.3V
C381 "100nF" C0402_CAPC1005L 153.897,92.4 r0 top
C382 "100nF" C0402_CAPC1005L 153.897,91.55 r0 top
C383 "0455-Cap-1206-100uF/6.3V" C/1206 158.749,106.9 r90 bottom value=100uF/6.3V
C384 "0455-Cap-1206-100uF/6.3V" C/1206 156.4,106.9 r90 bottom value=100uF/6.3V
C385 "1646-Cap-0402-10uF/6.3V" C0402_CAPC1005L 153.9,107.45 r0 top value=10uF/6.3V
C386 "1646-Cap-0402-10uF/6.3V" C0402_CAPC1005L 153.9,106.55 r0 top value=10uF/6.3V
C387 "100nF" C0402_CAPC1005L 153.9,105.75 r0 top
C388 "100nF" C0402_CAPC1005L 153.9,104.85 r0 top
C389 "100nF" C0402_CAPC1005L 42.49,143.871 r0 top
C390 "100nF" C0402_CAPC1005L 41.1,142.2 r270 top
C391 "1646-Cap-0402-10uF/6.3V" C0402_CAPC1005L 49.5,140.5 r0 top value=10uF/6.3V
C392 "100nF" C0402_CAPC1005L 50.7,140.9 r270 top
C393 "1646-Cap-0402-10uF/6.3V" C0402_CAPC1005L 168.083,159.885 r90 top value=10uF/6.3V
C394 "100nF" C0402_CAPC1005L 169.5,160.675 r270 top
D1 "SMAJ28CA" SMAJ_TRANSIL 14.382,185.51 r180 top
D2 "Status" LED-SMT-0603_APT1608CGCK 19.575,170.325 r180 top
D3 "SDT15H50P5-13" POWERDI-5_DIO 12.852,151.222 r180 top
D4 "Status" LED-SMT-0603_APT1608CGCK 19.575,180.45 r180 top
D5 "Status" LED-SMT-0603_APT1608CGCK 19.575,175.35 r180 top
D6 "Status" LED-SMT-0603_APT1608CGCK 19.575,172 r180 top
D7 "Status" LED-SMT-0603_APT1608CGCK 19.575,173.675 r180 top
D8 "D5V0L1B2S9-7" SOD923_DIO 236.569,14.162 r180 top locked
D9 "Status" LED-SMT-0603_APT1608CGCK 19.6,166.975 r180 top
D10 "BAT54XV2T5G" SOD523_SC79 48.765,141.865 r0 top
D11 "Status" LED-SMT-0603_APT1608CGCK 49.84,181.453 r270 top
D12 "BAT54C" SOT23_M 38.245,170.884 r270 top
D13 "BAT54XV2T5G" SOD523_SC79 169.5,158.55 r90 top
D14 "Status" LED-SMT-0603_APT1608CGCK 93.6,24.1 r0 top
D15 "D5V0L1B2S9-7" SOD923_DIO 229.307,14.225 r180 top locked
D16 "BAT54C" SOT23_M 138.315,170.703 r180 top
D17 "BAT54C" SOT23_M 157.096,172.565 r90 top
D18 "Status" LED-SMT-0603_APT1608CGCK 144.37,179.521 r180 top
D19 "BAT54C" SOT23_M 104.664,151.149 r270 top
D20 "Status" LED-SMT-0603_APT1608CGCK 115.171,157.419 r180 top
D21 "Status" LED-SMT-0603_APT1608CGCK 115.171,165.043 r180 top
D22 "BAT54C" SOT23_M 69.876,163.304 r270 top
D23 "BAT54C" SOT23_M 172.987,3.89 r90 top
D24 "Status" LED-SMT-0603_APT1608CGCK 19.575,168.65 r180 top
D25 "Status" LED-SMT-0603_APT1608CGCK 158.7,2.93 r90 top
D26 "Status" LED-SMT-0603_APT1608CGCK 157.056,2.93 r90 top
D27 "BAT54C" SOT23_M 174.121,91.374 r180 top
D28 "BAT54C" SOT23_M 29.55,166.6 r90 top
D29 "Status" LED-SMT-0603_APT1608CGCK 169.566,105.65 r180 top
D30 "Status" LED-SMT-0603_APT1608CGCK 169.6,103.988 r180 top
D31 "SMAJ28CA" SMAJ_TRANSIL 198.022,160.9 r0 top
D32 "BAT54C" SOT23_M 178.9,3.871 r90 top
D33 "D5V0L1B2S9-7" SOD923_DIO 222.046,14.214 r0 top locked
D34 "Status" LED-SMT-0603_APT1608CGCK 19.6,165.3 r180 top
D35 "D5V0L1B2S9-7" SOD923_DIO 214.801,14.22 r0 top locked
D36 "D5V0L1B2S9-7" SOD923_DIO 126.332,190.09 r180 top
D37 "D5V0L1B2S9-7" SOD923_DIO 112.834,190.481 r270 bottom
D38 "D5V0L1B2S9-7" SOD923_DIO 112.834,188.294 r90 bottom
D39 "ASMB-MTB0-0B3A2" 4-PLCC 226.74,38.7 r180 top
D40 "ASMB-MTB0-0B3A2" 4-PLCC 223.14,38.7 r180 top
D41 "ASMB-MTB0-0B3A2" 4-PLCC 219.49,38.65 r180 top
D42 "ASMB-MTB0-0B3A2" 4-PLCC 215.89,38.65 r180 top
D43 "D5V0L1B2S9-7" SOD923_DIO 24.2,97.675 r180 top
D44 "BZX84-C12" SOT23_N 29.35,146.575 r90 top value=12V
D45 "Status" LED-SMT-0603_APT1608CGCK 126.482,196.975 r90 top
D46 "1N4148W" SOD123_ALT 13.59,173.145 r270 top
D47 "BAT54C" SOT23_M 169.771,91.374 r180 top
D48 "Status" LED-SMT-0603_APT1608CGCK 19.575,178.75 r180 top
D49 "Status" LED-SMT-0603_APT1608CGCK 19.575,177.05 r180 top
D50 "D5V0L1B2S9-7" SOD923_DIO 143.12,184.355 r180 top
F1 "15A Slow" FUSE_1206_(3216) 9.975,182.5 r180 top value=15A/63VDC
F2 "7A Slow" R/1206 18.3,150.525 r90 top
FID1 "d=1.0mm" FID_40X120_RND 188.775,183.575 r0 bottom
FID2 "d=1.0mm" FID_40X120_RND 188.775,183.575 r270 top
FID3 "d=1.0mm" FID_40X120_RND 245,69 r270 top
FID4 "d=1.0mm" FID_40X120_RND 37.9,136.988 r270 bottom
FID5 "d=1.0mm" FID_40X120_RND 245,69 r270 bottom
FID6 "d=1.0mm" FID_40X120_RND 37.9,136.988 r270 top
H1 "Hole" MTG_HOLE_0.125 5,5 r180 top locked
H2 "Hole" MTG_HOLE_0.125 5,195 r180 top locked
H3 "Hole" MTG_HOLE_0.125 245,195 r180 top locked
H4 "Hole" MTG_HOLE_0.125 245,5 r180 top locked
J1 "61302021121" WURTH_61302021121 59.03,70.45 r90 top locked
J1A "61301011821" WURTH_61301011821 65.38,70.45 r90 top
J1B "61301011821" WURTH_61301011821 52.68,70.45 r90 top
J2 "61302021121" WURTH_61302021121 59.03,42.59 r90 top locked
J2A "61301011821" WURTH_61301011821 65.38,42.59 r90 top
J2B "61301011821" WURTH_61301011821 52.68,42.59 r90 top
J3 "61302021121" WURTH_61302021121 153.47,133.16 r180 top
J3A "61301011821" WURTH_61301011821 153.47,126.81 r180 top
J3B "61301011821" WURTH_61301011821 153.47,139.51 r180 top
J4 "61302421121" WURTH_61302421121 195.82,95.77 r90 top locked
J4A "61301211821" WURTH_61301211821 189.47,95.77 r90 top
J4B "61301211821" WURTH_61301211821 202.17,95.77 r90 top
J5 "61302021121" WURTH_61302021121 59.08,14.73 r90 top locked
J5A "61301011821" WURTH_61301011821 65.43,14.73 r90 top
J5B "61301011821" WURTH_61301011821 52.73,14.73 r90 top
J6 "61302421121" WURTH_61302421121 195.82,62.83 r270 top locked
J6A "61301211821" WURTH_61301211821 189.47,62.83 r270 top
J6B "61301211821" WURTH_61301211821 202.17,62.83 r270 top
J7 "61302021121" WURTH_61302021121 59.03,98.31 r90 top locked
J7A "61301011821" WURTH_61301011821 65.38,98.31 r90 top
J7B "61301011821" WURTH_61301011821 52.68,98.31 r90 top
J8 "61302421121" WURTH_61302421121 195.82,128.71 r270 top
J8A "61301211821" WURTH_61301211821 189.47,128.71 r270 top
J8B "61301211821" WURTH_61301211821 202.17,128.71 r270 top
J9 "61302021121" WURTH_61302021121 94.75,133.16 r0 top
J9A "61301011821" WURTH_61301011821 94.75,126.81 r0 top
J9B "61301011821" WURTH_61301011821 94.75,139.51 r0 top
J10 "61300821121" WURTH_61300821121 59.03,118.55 r90 top locked
J10A "61300411821" WURTH_61300411821 65.38,118.55 r90 top
J10B "61300411821" WURTH_61300411821 52.68,118.55 r90 top
J11 "61300821121" WURTH_61300821121 125.61,133.16 r0 top
J11A "61300411821" WURTH_61300411821 125.61,126.81 r0 top
J11B "61300411821" WURTH_61300411821 125.61,139.51 r0 top
J12 "61302021121" WURTH_61302021121 195.82,32.43 r270 top locked
J12A "61301011821" WURTH_61301011821 189.47,32.43 r270 top
J12B "61301011821" WURTH_61301011821 202.17,32.43 r270 top
J13 "61301011821" WURTH_61301011821 153.58,158.25 r0 top
J14 "61301221121" WURTH_61301221121 195.83,9.65 r270 top locked
J14A "61300611821" WURTH_61300611821 189.48,9.65 r270 top
J14B "61300611821" WURTH_61300611821 202.18,9.65 r270 top
J15 "61300611821" WURTH_61300611821 35.277,103.554 r270 top
J16 "61300611821" WURTH_61300611821 30.977,103.554 r270 top
J17 "1923759" PHOENIX_1923759 14.635,190.009 r180 top locked
J18 "1250-Conn-Hdr-1x2 TH Vert" CON_HDR1X2 179.875,172.1 r0 top
J19 "61300821121" WURTH_61300821121 77.199,21.175 r90 top
J20 "691137710002" WURTH_691137710002 179.2,196.2 r180 top
J21 "68001-203HLF" CON_HDR1X3 22.26,157.525 r90 top
J22 "000-Hdr-2pin" HDR1X2 33.647,86.913 r180 top
J23 "USB4105-GF-A-120" GCT_USB4105GFA120 43.75,195 r180 top
J24 "000-Hdr-4pin" HDR1X4 45.15,147.275 r0 top
J25 "000-Hdr-5pin" HDR1X5 57.005,147.275 r180 top
J26 "000-Hdr-4pin" HDR1X4 45.325,152.325 r180 top
J27 "0472720001" MOLEX_47272-0001 208.75,191.567 r180 top locked
J28 "000-Hdr-2pin" HDR1X2 73.602,180.315 r180 top
J29 "67996-200HLF" CON_HDR1X2 14.051,14.508 r90 top
J30 "SD-4-B" SD-4-B 108.475,14.25 r180 bottom locked
J31 "000-Hdr-2pin" HDR1X2 75.875,137.95 r0 top
J32 "12401826E412A" AMPHENOL_12401826E412A 133,195.23 r180 top locked
J33 "GSB4112312HR" "T_AMPHENOL_ GSB311231HR" 103.28,188.65 r180 top
J34 "JXD0-0025NL" PULSE_JXD0-0025NL 60.95,192 r180 top locked
J35 "000-Hdr-3pin" HDR1X3 86.36,166.2 r90 top
J36 "JXD0-0025NL" PULSE_JXD0-0025NL 82.7,192 r180 top locked
J37 "000-Hdr-4pin" HDR1X4 164.06,20.05 r0 top
J38 "000-Hdr-4pin" HDR1X4 164.06,17 r0 top
J39 "MDT275B03001" AMPHENOL_MDT275B03001_TYPE_3052 149.325,15.275 r270 top locked
J40 "000-Hdr-4pin" HDR1X4 150.97,2.4 r180 top
J41 "000-Hdr-3pin" HDR1X3 162.79,14.125 r0 top
J42 "0737-Conn-MicroSIM" "MICROSD 0787231001" 132,12.255 r270 bottom locked
J43 "MDT420M01501" AMPHENOL_MDT420M01501 159.825,100.8 r270 top locked
J44 "LSS-130-03-L-DV-A-K-TR" SAMTEC_LSS-130-03-L-DV-A-K-TR_ALT 206.1,156.15 r180 top locked
J45 "67996-200HLF" CON_HDR1X2 33.434,14.55 r90 top
J46 "SJ-43515TS" CUI_SJ-43515TS 235.625,194.5 r270 top locked
J47 "61300621821" WURTH_61300621821 53.95,129.9 r90 top
J48 "61300621821" WURTH_61300621821 174.68,65.435 r90 top locked
J49 "67996-200HLF" CON_HDR1X2 17.501,14.508 r90 top
J50 "61300411821" WURTH_61300411821 247.075,26.04 r270 top
J51 "000-Hdr-2pin" HDR1X2 161.507,29 r0 top
J52 "000-Hdr-3pin" HDR1X3 162.777,26.05 r0 top
J53 "61300411821" WURTH_61300411821 239.425,63.775 r0 top
J54 "000-Hdr-4pin" HDR1X4 164.06,23.075 r0 top
J55 "61300611821" WURTH_61300611821 220.995,55.825 r0 top
J56 "0470531000" CONN_47053-1000_MOL 176.02,29.045 r90 top
J57 "000-Hdr-4pin" HDR1X4 92.07,29.62 r0 top
J58 "67996-200HLF" CON_HDR1X2 77.28,51.388 r0 top
J59 "1389-Conn-Header 5X2 SMT Vert" SAMTEC_FTSH-105-01-L-DV-007 77.8,60.5 r270 top
J60 "61301011821" WURTH_61301011821 227.4,128.45 r270 top
J61 "61301011821" WURTH_61301011821 245.05,128.45 r270 top
J62 "000-Hdr-3pin" HDR1X3 173.946,102.3 r270 top
J63 "67996-200HLF" CON_HDR1X2 56.7,140.5 r270 top
J64 "67996-200HLF" CON_HDR1X2 36.9,14.55 r90 top
J65 "USB4105-GF-A-120" GCT_USB4105GFA120 28,195 r180 top
J66 "67996-200HLF" CON_HDR1X2 178.875,186.925 r0 top
J67 "L717SDEH09POL2RM8" "DSUB_A-DS 09 A/KG-T2S" 157.465,190.48 r180 top locked
J68 "67996-200HLF" CON_HDR1X2 14.5,45.15 r0 top
J69 "000-Hdr-7pin" HDR1X7 240.06,156.4 r0 top
J70 "FH12-24S-0.5SVA(54)" HIROSE_FH12-24S-0.5SVA(54) 244.9,104.24 r90 top locked
J71 "FH12-24S-0.5SVA(54)" HIROSE_FH12-24S-0.5SVA(54) 244.9,84.98 r90 top
J72 "12401826E412A" AMPHENOL_12401826E412A 120,195.23 r180 top locked
J73 "67996-200HLF" CON_HDR1X2 14.5,26.483 r0 top
J74 "67996-200HLF" CON_HDR1X2 14.5,48.6 r0 top
J75 "67996-200HLF" CON_HDR1X2 14.5,29.966 r0 top
J76 "67996-200HLF" CON_HDR1X2 175.61,10.274 r180 top
J77 "61301021121" WURTH_61301021121 15.796,2.913 r0 top
J78 "61301021121" WURTH_61301021121 35.235,2.9 r0 top
J79 "67996-200HLF" CON_HDR1X2 10.701,9.608 r270 top
J80 "67996-200HLF" CON_HDR1X2 20.551,9.583 r90 top
J81 "67996-200HLF" CON_HDR1X2 30.125,9.575 r270 top
J82 "67996-200HLF" CON_HDR1X2 39.75,9.545 r90 top
J83 "61301021121" WURTH_61301021121 2.893,28.283 r270 top
J84 "61301021121" WURTH_61301021121 2.893,46.7 r270 top
J85 "67996-200HLF" CON_HDR1X2 9,33.35 r180 top
J86 "67996-200HLF" CON_HDR1X2 9,24 r0 top
J87 "68001-203HLF" CON_HDR1X3 168.6,173.1 r180 top locked
J88 "000-Hdr-2pin" HDR1X2 33.825,186.9 r0 top
J89 "67996-200HLF" CON_HDR1X2 9,51.8 r180 top
J90 "67996-200HLF" CON_HDR1X2 9,42.417 r0 top
J91 "68001-203HLF" CON_HDR1X3 176.4,15 r180 top
J92 "67996-200HLF" CON_HDR1X2 237.862,151.02 r180 top
J94 "61300611821" WURTH_61300611821 175.95,51.465 r90 top
J95 "821-22-005-10-004101" POGO_821-22-005_MILL_MAX 166.25,72.42 r90 top locked
J96 "61300611821" WURTH_61300611821 173.41,51.465 r90 top
J97 "821-22-005-10-004101" POGO_821-22-005_MILL_MAX 83.75,72.42 r90 top locked
JP1 "Short" SHORT_040 139.42,182.386 r270 top net-tie
JP2 "Short" SHORT_040 235.325,182.125 r90 top net-tie
JP3 "Short" SHORT_040 209.625,147.5 r270 top net-tie
JP4 "Short" SHORT_040 211,147.5 r270 top net-tie
L1 "83 ohm/21A" WE-CMS_9085 14.29,159.222 r270 top
L4 "EXL1V0705-4R7-R" EATON_EXL1V0705-4R7-R 6.025,66.725 r90 top value=4.7uH/11A
L5 "1618-Ind-1210-1uH/5.5A" INDC3225N 8.275,84.85 r0 top value=1uH/5.5A
L6 "EXL1V0705-4R7-R" EATON_EXL1V0705-4R7-R 9.541,104.075 r270 top value=4.7uH/11A
L9 "2229-Ind-13.5x12.5-2.2uH/22A" IND_SRP1265A-LF_BRN 11.945,133.44 r90 top value=2.2uH/22A
L10 "2247-Fer-0402-5ohm/0.5A" R0402_RESC1005L 237.225,184.9 r90 top value=5ohm/0.5A
L11 "2247-Fer-0402-5ohm/0.5A" R0402_RESC1005L 232.575,183.875 r90 top value=5ohm/0.5A
L12 "2247-Fer-0402-5ohm/0.5A" R0402_RESC1005L 242.475,183.675 r270 top value=5ohm/0.5A
L13 "0405-Fer-0603-330ohm/1.7A" C/0603 47.391,188.992 r0 top value="330 ohm/1.7A"
L14 "90 ohm/0.4A" COMMON_CHOKE_BOURNS_SRF2012-900YA 43.725,182.205 r90 top
L15 "0405-Fer-0603-330ohm/1.7A" C/0603 40.755,170.097 r90 top value="330 ohm/1.7A"
L16 "0405-Fer-0603-330ohm/1.7A" C/0603 40.765,165.225 r0 top value="330 ohm/1.7A"
L17 "0405-Fer-0603-330ohm/1.7A" C/0603 40.765,161.725 r0 top value="330 ohm/1.7A"
L18 "0405-Fer-0603-330ohm/1.7A" C/0603 40.765,163.475 r0 top value="330 ohm/1.7A"
L19 "0405-Fer-0603-330ohm/1.7A" C/0603 40.765,159.975 r0 top value="330 ohm/1.7A"
L20 "0405-Fer-0603-330ohm/1.7A" C/0603 108.664,32.43 r270 bottom value="330 ohm/1.7A"
L21 "0405-Fer-0603-330ohm/1.7A" C/0603 76.2,127.425 r180 top value="330 ohm/1.7A"
L22 "12 ohm/0.1A" COIL0302 137.4,186.8 r0 top
L23 "12 ohm/0.1A" COIL0302 135.875,186.8 r0 top
L26 "0405-Fer-0603-330ohm/1.7A" C/0603 157.096,177.265 r180 top value="330 ohm/1.7A"
L28 "12 ohm/0.1A" COIL0302 130.9,186.8 r0 top
L29 "12 ohm/0.1A" COIL0302 129.4,186.8 r0 top
L30 "90 ohm/0.4A" COMMON_CHOKE_BOURNS_SRF2012-900YA 133,185.825 r270 top
L31 "0405-Fer-0603-330ohm/1.7A" C/0603 89.976,147.186 r180 top value="330 ohm/1.7A"
L32 "0405-Fer-0603-330ohm/1.7A" C/0603 124.931,158.312 r180 top value="330 ohm/1.7A"
L33 "0405-Fer-0603-330ohm/1.7A" C/0603 124.95,165.863 r180 top value="330 ohm/1.7A"
L34 "12R/0.1A" COIL0302 100.28,177.4 r180 top
L35 "12R/0.1A" COIL0302 102.975,177.4 r180 top
L36 "90R/0.4A" COMMON_CHOKE_BOURNS_SRF2012-900YA 104.475,177.4 r270 top
L37 "12R/0.1A" COIL0302 95.025,177.4 r180 top
L38 "12R/0.1A" COIL0302 96.8,177.4 r180 top
L39 "90R/0.4A" COMMON_CHOKE_BOURNS_SRF2012-900YA 98.78,177.4 r270 top
L41 "0405-Fer-0603-330ohm/1.7A" C/0603 74.27,158.66 r180 top value="330 ohm/1.7A"
L42 "0405-Fer-0603-330ohm/1.7A" C/0603 80.075,154.323 r180 top value="330 ohm/1.7A"
L43 "2247-Fer-0402-5ohm/0.5A" R0402_RESC1005L 242.925,167.725 r270 top value=5ohm/0.5A
L45 "2247-Fer-0402-5ohm/0.5A" R0402_RESC1005L 244.6,167.675 r270 top value=5ohm/0.5A
L46 "0405-Fer-0603-330ohm/1.7A" C/0603 157.756,8.322 r180 top value="330 ohm/1.7A"
L47 "0405-Fer-0603-330ohm/1.7A" C/0603 157.756,10.022 r180 top value="330 ohm/1.7A"
L48 "0405-Fer-0603-330ohm/1.7A" C/0603 169.678,109.179 r180 top value="330 ohm/1.7A"
L49 "0405-Fer-0603-330ohm/1.7A" C/0603 169.678,110.829 r180 top value="330 ohm/1.7A"
L50 "12R/0.1A" COIL0302 200.385,152.2 r0 top
L51 "12R/0.1A" COIL0302 202.29,152.2 r0 top
L52 "12R/0.1A" COIL0302 204.195,152.2 r0 top
L53 "12R/0.1A" COIL0302 206.1,152.2 r0 top
L54 "12R/0.1A" COIL0302 208.005,152.2 r0 top
L55 "0405-Fer-0603-330ohm/1.7A" C/0603 202.672,165.45 r0 top value="330 ohm/1.7A"
L56 "0405-Fer-0603-330ohm/1.7A" C/0603 39.325,25.55 r180 top value="330 ohm/1.7A"
L57 "0405-Fer-0603-330ohm/1.7A" C/0603 39.375,27.15 r180 top value="330 ohm/1.7A"
L58 "220 ohm/0.3A" COMMON_CHOKE_BOURNS_SRF2012-900YA 15.776,10.183 r90 top
L59 "220 ohm/0.3A" COMMON_CHOKE_BOURNS_SRF2012-900YA 35.2,10.2 r90 top
L60 "0405-Fer-0603-330ohm/1.7A" C/0603 237.4,169.7 r90 top value="330 ohm/1.7A"
L61 "0405-Fer-0603-330ohm/1.7A" C/0603 238.015,179.56 r270 top value="330 ohm/1.7A"
L62 "0405-Fer-0603-330ohm/1.7A" C/0603 220.413,97.632 r90 top value="330 ohm/1.7A"
L63 "0405-Fer-0603-330ohm/1.7A" C/0603 77.445,36.865 r180 top value="330 ohm/1.7A"
L66 "0405-Fer-0603-330ohm/1.7A" C/0603 101.675,55.525 r270 top value="330 ohm/1.7A"
L71 "0405-Fer-0603-330ohm/1.7A" C/0603 38.55,49.125 r180 top value="330 ohm/1.7A"
L72 "0405-Fer-0603-330ohm/1.7A" C/0603 38.55,44.575 r180 top value="330 ohm/1.7A"
L73 "220 ohm/0.3A" COMMON_CHOKE_BOURNS_SRF2012-900YA 10.207,46.542 r0 top
L74 "220 ohm/0.3A" COMMON_CHOKE_BOURNS_SRF2012-900YA 10.2,28.125 r0 top
L75 "0405-Fer-0603-330ohm/1.7A" C/0603 222.4,177.392 r180 top value="330 ohm/1.7A"
L76 "12R/0.1A" COIL0302 203.75,180.717 r0 top
L77 "1652-Fer-42ohm/10A" FB_35F0121-0SR-10 22.5,186.68 r270 top value=42ohm/10A
L78 "0405-Fer-0603-330ohm/1.7A" C/0603 174.375,175.425 r90 top value="330 ohm/1.7A"
L79 "0405-Fer-0603-330ohm/1.7A" C/0603 167.025,179.35 r180 top value="330 ohm/1.7A"
L80 "0405-Fer-0603-330ohm/1.7A" C/0603 174.373,178.8 r90 top value="330 ohm/1.7A"
L81 "12R/0.1A" COIL0302 235.775,109.5 r270 top
L82 "12R/0.1A" COIL0302 235.775,108 r270 top
L83 "12R/0.1A" COIL0302 235.775,106.5 r270 top
L84 "12R/0.1A" COIL0302 235.775,102.5 r270 top
L85 "12R/0.1A" COIL0302 235.775,100.375 r270 top
L86 "12R/0.1A" COIL0302 235.775,90.24 r270 top
L87 "12R/0.1A" COIL0302 235.775,88.74 r270 top
L88 "12R/0.1A" COIL0302 235.775,87.24 r270 top
L89 "12R/0.1A" COIL0302 235.775,83.24 r270 top
L90 "12R/0.1A" COIL0302 235.775,81.115 r270 top
L91 "0405-Fer-0603-330ohm/1.7A" C/0603 107.71,173.661 r90 top value="330 ohm/1.7A"
L92 "0405-Fer-0603-330ohm/1.7A" C/0603 116.199,172.149 r180 top value="330 ohm/1.7A"
L94 "12 ohm/0.1A" COIL0302 122.775,186.8 r0 top
L95 "12 ohm/0.1A" COIL0302 124.3,186.8 r0 top
L96 "12 ohm/0.1A" COIL0302 116.4,186.8 r0 top
L97 "12 ohm/0.1A" COIL0302 117.9,186.8 r0 top
L99 "90R/0.4A" COMMON_CHOKE_BOURNS_SRF2012-900YA 119.925,185.825 r270 top
L100 "12R/0.1A" COIL0302 205.25,180.717 r0 top
L101 "12R/0.1A" COIL0302 206.75,180.717 r0 top
L102 "12R/0.1A" COIL0302 208.25,180.717 r0 top
L103 "12R/0.1A" COIL0302 210.75,180.717 r0 top
LBL1 "SN Label 0.25x0.9 inch" LABEL_0.25X0.9IN 178.5,116.1 r90 top
M1 "APM6-100-01.5-L-04-0-A-FR" SAMTEC_APM-100-01.5-L04-0-A 125,81.5 r0 top locked
ME1 "9774080360R" WURTH_9774080360R 190.1,195.15 r270 top
ME2 "9774080360R" WURTH_9774080360R 190.1,153.15 r270 top locked
ME3 "9774080360R" WURTH_9774080360R 222.1,153.15 r270 top
ME4 "9774080360R" WURTH_9774080360R 222.1,195.15 r270 top
ME5 "2405-Post-M3-5mm" "MTG_POST WURTH 9774050360R" 163.994,5 r270 top locked
ME6 "2405-Post-M3-5mm" "MTG_POST WURTH 9774050360R" 163.994,35 r270 top locked
ME7 "2405-Post-M3-5mm" "MTG_POST WURTH 9774050360R" 163.994,83 r270 top locked
ME8 "2405-Post-M3-5mm" "MTG_POST WURTH 9774050360R" 85.994,83 r270 top locked
ME9 "2405-Post-M3-5mm" "MTG_POST WURTH 9774050360R" 85.994,35 r270 top locked
ME10 "2405-Post-M3-5mm" "MTG_POST WURTH 9774050360R" 85.994,5 r270 top locked
ME11 "2405-Post-M3-5mm" "MTG_POST WURTH 9774050360R" 85.994,50 r270 top locked
ME12 "2405-Post-M3-5mm" "MTG_POST WURTH 9774050360R" 163.994,50 r270 top locked
ME13 "9774005243R" MECH-WURTH-9774005243R 120.25,15.275 r0 top locked
ME14 "9774005243R" MECH-WURTH-9774005243R 108.25,15.275 r0 top locked
ME15 "9774005243R" MECH-WURTH-9774005243R 98.25,15.275 r0 top locked
ME18 "9774005243R" MECH-WURTH-9774005243R 80.075,100.8 r0 top
MP1 "SJ61A3" 3M-SJ61A3 245,5 r180 bottom
MP2 "SJ61A3" 3M-SJ61A3 124.994,83 r180 bottom
MP3 "SJ61A3" 3M-SJ61A3 124.994,26.675 r180 bottom
MP4 "SJ61A3" 3M-SJ61A3 5,5 r180 bottom
MP5 "SJ61A3" 3M-SJ61A3 163.994,50 r180 bottom
MP6 "SJ61A3" 3M-SJ61A3 85.994,50 r180 bottom
MP7 "SJ61A3" 3M-SJ61A3 5,193 r180 bottom
MP8 "SJ61A3" 3M-SJ61A3 85.994,148.25 r180 bottom
MP9 "SJ61A3" 3M-SJ61A3 245,193 r180 bottom
MP10 "SJ61A3" 3M-SJ61A3 163.994,148.25 r180 bottom
Q1 "CSD18511Q5A" "VSONP-8 (5X6)" 4.795,177.43 r90 top
Q2 "CSD18511Q5A" "VSONP-8 (5X6)" 4.795,170.124 r270 top
Q3 "DMP26M7UFG-7" DMP3008 37.625,77.775 r0 top
Q4 "FDV301N" SOT23 35.3,73.275 r0 top
Q5 "FDV301N" SOT23 33.564,137.2 r90 top
Q6 "FDV301N" SOT23 158.889,58.948 r180 bottom
Q7 "NTZD3155CT1G" SOTFL50P160X60-6N 30.25,75.55 r180 top
Q8 "FDV301N" SOT23 18.85,86.65 r270 top
Q9 "NTZD3154" SOT563 80.475,31.375 r90 top
Q10 "NTZD3154" SOT563 75.509,31.356 r90 top
Q11 "NTZD3154" SOT563 78.095,31.375 r90 top
Q12 "NTZD3154" SOT563 159.071,175.615 r0 top
Q13 "DMP3099L" SOT23_N 97.996,151.724 r90 top
Q14 "MMBT5551M3T5G" SOT-723_0P85X1P25_ONS 94.07,154.21 r180 top
Q15 "NTZD3154" SOT563 73.321,182.623 r90 bottom
Q16 "MMBT5551M3T5G" SOT-723_0P85X1P25_ONS 10.48,168.827 r0 top
Q17 "IRLML0040" SOT23 172.125,20.75 r180 top
Q18 "NTZD3154" SOT563 218.11,44.95 r270 top
Q19 "NTZD3154" SOT563 225.425,44.6 r270 top
Q21 "FDV301N" SOT23 36.15,180.05 r270 top
Q22 "CSD18503Q5A" "VSONP-8 (5X6)" 5.222,122.92 r180 top
Q23 "CSD18511Q5A" "VSONP-8 (5X6)" 12.612,122.92 r180 top
Q24 "2217-IRF9358TRPBF" SOIC-8 23.4,147.025 r180 top locked
Q25 "MMBT5551M3T5G" SOT-723_0P85X1P25_ONS 10.88,170.991 r0 top
Q26 "2N7002" SOT23 27.6,161.556 r180 top
Q27 "2N7002" SOT23 25.975,165.925 r0 top
Q28 "FDV301N" SOT23 119.467,179.192 r180 top
Q29 "FDV301N" SOT23 137.13,175.286 r180 top
Q30 "NTZD3155CT1G" SOTFL50P160X60-6N 69.576,170.179 r270 top
Q31 "NTZD3154" SOT563 76.025,54.975 r180 top
Q32 "NTZD3154" SOT563 83.075,27.175 r90 top
R1 "1809-Res-0402-887K" R0402_RESC1005L 4.141,153.672 r0 top value=887K
R2 "1144-Res-0603-24.9K" R/0603 6.834,154.62 r180 top value=24.9K
R3 "1216-Res-0603-20K" R/0603 8.227,157.162 r270 top value=20K
R4 "1538-Res-0402-27k" R0402_RESC1005L 4.134,154.62 r0 top value=27K
R5 "1977-Res-0402-100K" R0402_RESC1005L 2.676,154.127 r90 top value=100K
